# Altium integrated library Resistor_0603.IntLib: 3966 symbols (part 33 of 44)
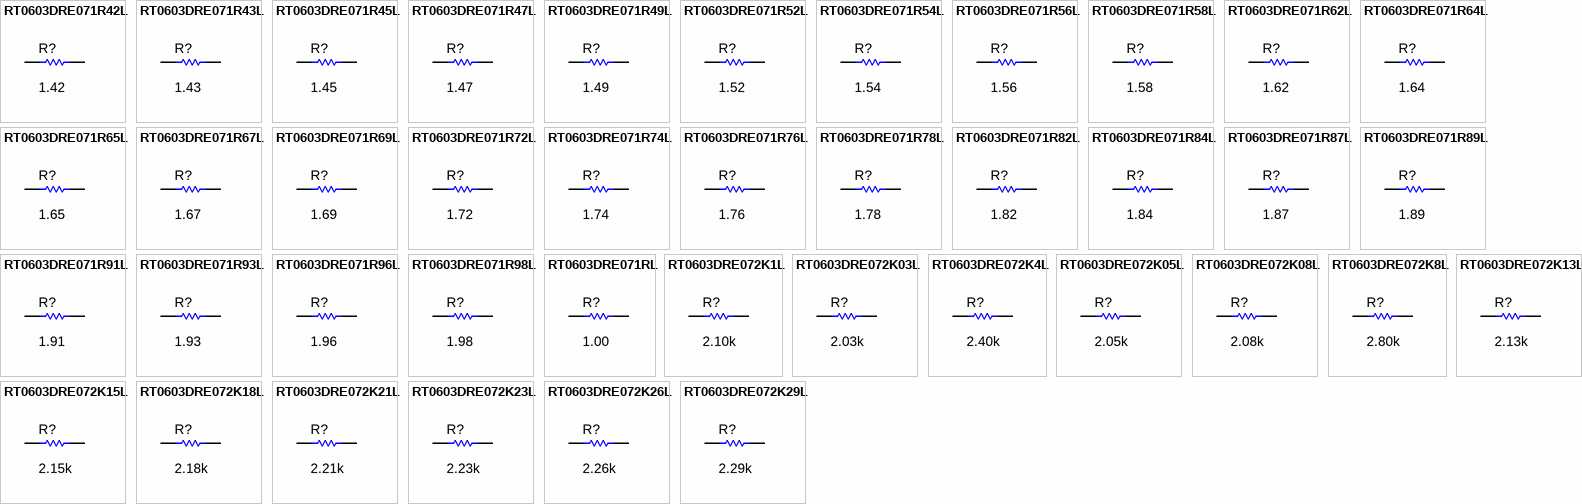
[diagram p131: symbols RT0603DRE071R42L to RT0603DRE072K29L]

## RT0603DRE071R49L
designator R?  ValueDisplayed: 1.49  (hidden comment: RT0603DRE071R49L)
RES, 1.49, 0.5%, 0.1 W, 0603; Manufacturer: Yageo America; CompType: Resistor; Value: 1.49; Value_Code: 1R49; Tolerance_%: 0.5; Power_W: 0.1; Value2: 0.1W; VDC_V: 75; TempCo: 50 ppm/C; SizeArea_mm2: 1.28; SizeX_mm: 1.6; SizeY_mm: 0.8; SizeZ_mm: 1; EIA_Code: E192; U/M: EA; AEC Category: Q200
signal-integrity model Resistor
simulation model Resistor
footprint 0603
footprint 0603M
footprint 0603L
footprint 0603_HV
footprint 0603S
pins: 1, 2

## RT0603DRE071R52L
designator R?  ValueDisplayed: 1.52  (hidden comment: RT0603DRE071R52L)
RES, 1.52, 0.5%, 0.1 W, 0603; Manufacturer: Yageo America; CompType: Resistor; Value: 1.52; Value_Code: 1R52; Tolerance_%: 0.5; Power_W: 0.1; Value2: 0.1W; VDC_V: 75; TempCo: 50 ppm/C; SizeArea_mm2: 1.28; SizeX_mm: 1.6; SizeY_mm: 0.8; SizeZ_mm: 1; EIA_Code: E192; U/M: EA; AEC Category: Q200
signal-integrity model Resistor
simulation model Resistor
footprint 0603
footprint 0603M
footprint 0603L
footprint 0603_HV
footprint 0603S
pins: 1, 2

## RT0603DRE071R54L
designator R?  ValueDisplayed: 1.54  (hidden comment: RT0603DRE071R54L)
RES, 1.54, 0.5%, 0.1 W, 0603; Manufacturer: Yageo America; CompType: Resistor; Value: 1.54; Value_Code: 1R54; Tolerance_%: 0.5; Power_W: 0.1; Value2: 0.1W; VDC_V: 75; TempCo: 50 ppm/C; SizeArea_mm2: 1.28; SizeX_mm: 1.6; SizeY_mm: 0.8; SizeZ_mm: 1; EIA_Code: E192; U/M: EA; AEC Category: Q200
signal-integrity model Resistor
simulation model Resistor
footprint 0603
footprint 0603M
footprint 0603L
footprint 0603_HV
footprint 0603S
pins: 1, 2

## RT0603DRE071R56L
designator R?  ValueDisplayed: 1.56  (hidden comment: RT0603DRE071R56L)
RES, 1.56, 0.5%, 0.1 W, 0603; Manufacturer: Yageo America; CompType: Resistor; Value: 1.56; Value_Code: 1R56; Tolerance_%: 0.5; Power_W: 0.1; Value2: 0.1W; VDC_V: 75; TempCo: 50 ppm/C; SizeArea_mm2: 1.28; SizeX_mm: 1.6; SizeY_mm: 0.8; SizeZ_mm: 1; EIA_Code: E192; U/M: EA; AEC Category: Q200
signal-integrity model Resistor
simulation model Resistor
footprint 0603
footprint 0603M
footprint 0603L
footprint 0603_HV
footprint 0603S
pins: 1, 2

## RT0603DRE071R58L
designator R?  ValueDisplayed: 1.58  (hidden comment: RT0603DRE071R58L)
RES, 1.58, 0.5%, 0.1 W, 0603; Manufacturer: Yageo America; CompType: Resistor; Value: 1.58; Value_Code: 1R58; Tolerance_%: 0.5; Power_W: 0.1; Value2: 0.1W; VDC_V: 75; TempCo: 50 ppm/C; SizeArea_mm2: 1.28; SizeX_mm: 1.6; SizeY_mm: 0.8; SizeZ_mm: 1; EIA_Code: E192; U/M: EA; AEC Category: Q200
signal-integrity model Resistor
simulation model Resistor
footprint 0603
footprint 0603M
footprint 0603L
footprint 0603_HV
footprint 0603S
pins: 1, 2

## RT0603DRE071R62L
designator R?  ValueDisplayed: 1.62  (hidden comment: RT0603DRE071R62L)
RES, 1.62, 0.5%, 0.1 W, 0603; Manufacturer: Yageo America; CompType: Resistor; Value: 1.62; Value_Code: 1R62; Tolerance_%: 0.5; Power_W: 0.1; Value2: 0.1W; VDC_V: 75; TempCo: 50 ppm/C; SizeArea_mm2: 1.28; SizeX_mm: 1.6; SizeY_mm: 0.8; SizeZ_mm: 1; EIA_Code: E192; U/M: EA; AEC Category: Q200
signal-integrity model Resistor
simulation model Resistor
footprint 0603
footprint 0603M
footprint 0603L
footprint 0603_HV
footprint 0603S
pins: 1, 2

## RT0603DRE071R64L
designator R?  ValueDisplayed: 1.64  (hidden comment: RT0603DRE071R64L)
RES, 1.64, 0.5%, 0.1 W, 0603; Manufacturer: Yageo America; CompType: Resistor; Value: 1.64; Value_Code: 1R64; Tolerance_%: 0.5; Power_W: 0.1; Value2: 0.1W; VDC_V: 75; TempCo: 50 ppm/C; SizeArea_mm2: 1.28; SizeX_mm: 1.6; SizeY_mm: 0.8; SizeZ_mm: 1; EIA_Code: E192; U/M: EA; AEC Category: Q200
signal-integrity model Resistor
simulation model Resistor
footprint 0603
footprint 0603M
footprint 0603L
footprint 0603_HV
footprint 0603S
pins: 1, 2

## RT0603DRE071R65L
designator R?  ValueDisplayed: 1.65  (hidden comment: RT0603DRE071R65L)
RES, 1.65, 0.5%, 0.1 W, 0603; Manufacturer: Yageo America; CompType: Resistor; Value: 1.65; Value_Code: 1R65; Tolerance_%: 0.5; Power_W: 0.1; Value2: 0.1W; VDC_V: 75; TempCo: 50 ppm/C; SizeArea_mm2: 1.28; SizeX_mm: 1.6; SizeY_mm: 0.8; SizeZ_mm: 1; EIA_Code: E192; U/M: EA; AEC Category: Q200
signal-integrity model Resistor
simulation model Resistor
footprint 0603
footprint 0603M
footprint 0603L
footprint 0603_HV
footprint 0603S
pins: 1, 2

## RT0603DRE071R67L
designator R?  ValueDisplayed: 1.67  (hidden comment: RT0603DRE071R67L)
RES, 1.67, 0.5%, 0.1 W, 0603; Manufacturer: Yageo America; CompType: Resistor; Value: 1.67; Value_Code: 1R67; Tolerance_%: 0.5; Power_W: 0.1; Value2: 0.1W; VDC_V: 75; TempCo: 50 ppm/C; SizeArea_mm2: 1.28; SizeX_mm: 1.6; SizeY_mm: 0.8; SizeZ_mm: 1; EIA_Code: E192; U/M: EA; AEC Category: Q200
signal-integrity model Resistor
simulation model Resistor
footprint 0603
footprint 0603M
footprint 0603L
footprint 0603_HV
footprint 0603S
pins: 1, 2

## RT0603DRE071R69L
designator R?  ValueDisplayed: 1.69  (hidden comment: RT0603DRE071R69L)
RES, 1.69, 0.5%, 0.1 W, 0603; Manufacturer: Yageo America; CompType: Resistor; Value: 1.69; Value_Code: 1R69; Tolerance_%: 0.5; Power_W: 0.1; Value2: 0.1W; VDC_V: 75; TempCo: 50 ppm/C; SizeArea_mm2: 1.28; SizeX_mm: 1.6; SizeY_mm: 0.8; SizeZ_mm: 1; EIA_Code: E192; U/M: EA; AEC Category: Q200
signal-integrity model Resistor
simulation model Resistor
footprint 0603
footprint 0603M
footprint 0603L
footprint 0603_HV
footprint 0603S
pins: 1, 2

## RT0603DRE071R72L
designator R?  ValueDisplayed: 1.72  (hidden comment: RT0603DRE071R72L)
RES, 1.72, 0.5%, 0.1 W, 0603; Manufacturer: Yageo America; CompType: Resistor; Value: 1.72; Value_Code: 1R72; Tolerance_%: 0.5; Power_W: 0.1; Value2: 0.1W; VDC_V: 75; TempCo: 50 ppm/C; SizeArea_mm2: 1.28; SizeX_mm: 1.6; SizeY_mm: 0.8; SizeZ_mm: 1; EIA_Code: E192; U/M: EA; AEC Category: Q200
signal-integrity model Resistor
simulation model Resistor
footprint 0603
footprint 0603M
footprint 0603L
footprint 0603_HV
footprint 0603S
pins: 1, 2

## RT0603DRE071R74L
designator R?  ValueDisplayed: 1.74  (hidden comment: RT0603DRE071R74L)
RES, 1.74, 0.5%, 0.1 W, 0603; Manufacturer: Yageo America; CompType: Resistor; Value: 1.74; Value_Code: 1R74; Tolerance_%: 0.5; Power_W: 0.1; Value2: 0.1W; VDC_V: 75; TempCo: 50 ppm/C; SizeArea_mm2: 1.28; SizeX_mm: 1.6; SizeY_mm: 0.8; SizeZ_mm: 1; EIA_Code: E192; U/M: EA; AEC Category: Q200
signal-integrity model Resistor
simulation model Resistor
footprint 0603
footprint 0603M
footprint 0603L
footprint 0603_HV
footprint 0603S
pins: 1, 2

## RT0603DRE071R76L
designator R?  ValueDisplayed: 1.76  (hidden comment: RT0603DRE071R76L)
RES, 1.76, 0.5%, 0.1 W, 0603; Manufacturer: Yageo America; CompType: Resistor; Value: 1.76; Value_Code: 1R76; Tolerance_%: 0.5; Power_W: 0.1; Value2: 0.1W; VDC_V: 75; TempCo: 50 ppm/C; SizeArea_mm2: 1.28; SizeX_mm: 1.6; SizeY_mm: 0.8; SizeZ_mm: 1; EIA_Code: E192; U/M: EA; AEC Category: Q200
signal-integrity model Resistor
simulation model Resistor
footprint 0603
footprint 0603M
footprint 0603L
footprint 0603_HV
footprint 0603S
pins: 1, 2

## RT0603DRE071R78L
designator R?  ValueDisplayed: 1.78  (hidden comment: RT0603DRE071R78L)
RES, 1.78, 0.5%, 0.1 W, 0603; Manufacturer: Yageo America; CompType: Resistor; Value: 1.78; Value_Code: 1R78; Tolerance_%: 0.5; Power_W: 0.1; Value2: 0.1W; VDC_V: 75; TempCo: 50 ppm/C; SizeArea_mm2: 1.28; SizeX_mm: 1.6; SizeY_mm: 0.8; SizeZ_mm: 1; EIA_Code: E192; U/M: EA; AEC Category: Q200
signal-integrity model Resistor
simulation model Resistor
footprint 0603
footprint 0603M
footprint 0603L
footprint 0603_HV
footprint 0603S
pins: 1, 2

## RT0603DRE071R82L
designator R?  ValueDisplayed: 1.82  (hidden comment: RT0603DRE071R82L)
RES, 1.82, 0.5%, 0.1 W, 0603; Manufacturer: Yageo America; CompType: Resistor; Value: 1.82; Value_Code: 1R82; Tolerance_%: 0.5; Power_W: 0.1; Value2: 0.1W; VDC_V: 75; TempCo: 50 ppm/C; SizeArea_mm2: 1.28; SizeX_mm: 1.6; SizeY_mm: 0.8; SizeZ_mm: 1; EIA_Code: E192; U/M: EA; AEC Category: Q200
signal-integrity model Resistor
simulation model Resistor
footprint 0603
footprint 0603M
footprint 0603L
footprint 0603_HV
footprint 0603S
pins: 1, 2

## RT0603DRE071R84L
designator R?  ValueDisplayed: 1.84  (hidden comment: RT0603DRE071R84L)
RES, 1.84, 0.5%, 0.1 W, 0603; Manufacturer: Yageo America; CompType: Resistor; Value: 1.84; Value_Code: 1R84; Tolerance_%: 0.5; Power_W: 0.1; Value2: 0.1W; VDC_V: 75; TempCo: 50 ppm/C; SizeArea_mm2: 1.28; SizeX_mm: 1.6; SizeY_mm: 0.8; SizeZ_mm: 1; EIA_Code: E192; U/M: EA; AEC Category: Q200
signal-integrity model Resistor
simulation model Resistor
footprint 0603
footprint 0603M
footprint 0603L
footprint 0603_HV
footprint 0603S
pins: 1, 2

## RT0603DRE071R87L
designator R?  ValueDisplayed: 1.87  (hidden comment: RT0603DRE071R87L)
RES, 1.87, 0.5%, 0.1 W, 0603; Manufacturer: Yageo America; CompType: Resistor; Value: 1.87; Value_Code: 1R87; Tolerance_%: 0.5; Power_W: 0.1; Value2: 0.1W; VDC_V: 75; TempCo: 50 ppm/C; SizeArea_mm2: 1.28; SizeX_mm: 1.6; SizeY_mm: 0.8; SizeZ_mm: 1; EIA_Code: E192; U/M: EA; AEC Category: Q200
signal-integrity model Resistor
simulation model Resistor
footprint 0603
footprint 0603M
footprint 0603L
footprint 0603_HV
footprint 0603S
pins: 1, 2

## RT0603DRE071R89L
designator R?  ValueDisplayed: 1.89  (hidden comment: RT0603DRE071R89L)
RES, 1.89, 0.5%, 0.1 W, 0603; Manufacturer: Yageo America; CompType: Resistor; Value: 1.89; Value_Code: 1R89; Tolerance_%: 0.5; Power_W: 0.1; Value2: 0.1W; VDC_V: 75; TempCo: 50 ppm/C; SizeArea_mm2: 1.28; SizeX_mm: 1.6; SizeY_mm: 0.8; SizeZ_mm: 1; EIA_Code: E192; U/M: EA; AEC Category: Q200
signal-integrity model Resistor
simulation model Resistor
footprint 0603
footprint 0603M
footprint 0603L
footprint 0603_HV
footprint 0603S
pins: 1, 2

## RT0603DRE071R91L
designator R?  ValueDisplayed: 1.91  (hidden comment: RT0603DRE071R91L)
RES, 1.91, 0.5%, 0.1 W, 0603; Manufacturer: Yageo America; CompType: Resistor; Value: 1.91; Value_Code: 1R91; Tolerance_%: 0.5; Power_W: 0.1; Value2: 0.1W; VDC_V: 75; TempCo: 50 ppm/C; SizeArea_mm2: 1.28; SizeX_mm: 1.6; SizeY_mm: 0.8; SizeZ_mm: 1; EIA_Code: E192; U/M: EA; AEC Category: Q200
signal-integrity model Resistor
simulation model Resistor
footprint 0603
footprint 0603M
footprint 0603L
footprint 0603_HV
footprint 0603S
pins: 1, 2

## RT0603DRE071R93L
designator R?  ValueDisplayed: 1.93  (hidden comment: RT0603DRE071R93L)
RES, 1.93, 0.5%, 0.1 W, 0603; Manufacturer: Yageo America; CompType: Resistor; Value: 1.93; Value_Code: 1R93; Tolerance_%: 0.5; Power_W: 0.1; Value2: 0.1W; VDC_V: 75; TempCo: 50 ppm/C; SizeArea_mm2: 1.28; SizeX_mm: 1.6; SizeY_mm: 0.8; SizeZ_mm: 1; EIA_Code: E192; U/M: EA; AEC Category: Q200
signal-integrity model Resistor
simulation model Resistor
footprint 0603
footprint 0603M
footprint 0603L
footprint 0603_HV
footprint 0603S
pins: 1, 2

## RT0603DRE071R96L
designator R?  ValueDisplayed: 1.96  (hidden comment: RT0603DRE071R96L)
RES, 1.96, 0.5%, 0.1 W, 0603; Manufacturer: Yageo America; CompType: Resistor; Value: 1.96; Value_Code: 1R96; Tolerance_%: 0.5; Power_W: 0.1; Value2: 0.1W; VDC_V: 75; TempCo: 50 ppm/C; SizeArea_mm2: 1.28; SizeX_mm: 1.6; SizeY_mm: 0.8; SizeZ_mm: 1; EIA_Code: E192; U/M: EA; AEC Category: Q200
signal-integrity model Resistor
simulation model Resistor
footprint 0603
footprint 0603M
footprint 0603L
footprint 0603_HV
footprint 0603S
pins: 1, 2

## RT0603DRE071R98L
designator R?  ValueDisplayed: 1.98  (hidden comment: RT0603DRE071R98L)
RES, 1.98, 0.5%, 0.1 W, 0603; Manufacturer: Yageo America; CompType: Resistor; Value: 1.98; Value_Code: 1R98; Tolerance_%: 0.5; Power_W: 0.1; Value2: 0.1W; VDC_V: 75; TempCo: 50 ppm/C; SizeArea_mm2: 1.28; SizeX_mm: 1.6; SizeY_mm: 0.8; SizeZ_mm: 1; EIA_Code: E192; U/M: EA; AEC Category: Q200
signal-integrity model Resistor
simulation model Resistor
footprint 0603
footprint 0603M
footprint 0603L
footprint 0603_HV
footprint 0603S
pins: 1, 2

## RT0603DRE071RL
designator R?  ValueDisplayed: 1.00  (hidden comment: RT0603DRE071RL)
RES, 1.00, 0.5%, 0.1 W, 0603; Manufacturer: Yageo America; CompType: Resistor; Value: 1.00; Res_ohm: 1; Value_Code: 1R00; Tolerance_%: 0.5; Power_W: 0.1; Value2: 0.1W; VDC_V: 75; TempCo: 50 ppm/C; SizeArea_mm2: 1.28; SizeX_mm: 1.6; SizeY_mm: 0.8; EIA_Code: E192; U/M: EA; AEC Category: Q200; Green_Lifecycle: Active; Green_REACh: Passed
signal-integrity model Resistor
simulation model Resistor
footprint 0603
footprint 0603M
footprint 0603L
footprint 0603_HV
footprint 0603S
pins: 1, 2

## RT0603DRE072K1L
designator R?  ValueDisplayed: 2.10k  (hidden comment: RT0603DRE072K1L)
RES, 2.10 k, 0.5%, 0.1 W, 0603; Manufacturer: Yageo America; CompType: Resistor; Value: 2.10k; Res_ohm: 2100; Value_Code: 2k10; Tolerance_%: 0.5; Power_W: 0.1; Value2: 0.1W; VDC_V: 75; TempCo: 50 ppm/C; SizeArea_mm2: 1.28; SizeX_mm: 1.6; SizeY_mm: 0.8; SizeZ_mm: 1; EIA_Code: E192; U/M: EA; AEC Category: Q200
signal-integrity model Resistor
simulation model Resistor
footprint 0603
footprint 0603M
footprint 0603L
footprint 0603_HV
footprint 0603S
pins: 1, 2

## RT0603DRE072K03L
designator R?  ValueDisplayed: 2.03k  (hidden comment: RT0603DRE072K03L)
RES, 2.03 k, 0.5%, 0.1 W, 0603; Manufacturer: Yageo America; CompType: Resistor; Value: 2.03k; Res_ohm: 2030; Value_Code: 2k03; Tolerance_%: 0.5; Power_W: 0.1; Value2: 0.1W; VDC_V: 75; TempCo: 50 ppm/C; SizeArea_mm2: 1.28; SizeX_mm: 1.6; SizeY_mm: 0.8; SizeZ_mm: 1; EIA_Code: E192; U/M: EA; AEC Category: Q200
signal-integrity model Resistor
simulation model Resistor
footprint 0603
footprint 0603M
footprint 0603L
footprint 0603_HV
footprint 0603S
pins: 1, 2

## RT0603DRE072K4L
designator R?  ValueDisplayed: 2.40k  (hidden comment: RT0603DRE072K4L)
RES, 2.40 k, 0.5%, 0.1 W, 0603; Manufacturer: Yageo America; CompType: Resistor; Value: 2.40k; Res_ohm: 2400; Value_Code: 2k40; Tolerance_%: 0.5; Power_W: 0.1; Value2: 0.1W; VDC_V: 75; TempCo: 50 ppm/C; SizeArea_mm2: 1.28; SizeX_mm: 1.6; SizeY_mm: 0.8; SizeZ_mm: 1; EIA_Code: E192; U/M: EA; AEC Category: Q200
signal-integrity model Resistor
simulation model Resistor
footprint 0603
footprint 0603M
footprint 0603L
footprint 0603_HV
footprint 0603S
pins: 1, 2

## RT0603DRE072K05L
designator R?  ValueDisplayed: 2.05k  (hidden comment: RT0603DRE072K05L)
RES, 2.05 k, 0.5%, 0.1 W, 0603; Manufacturer: Yageo America; CompType: Resistor; Value: 2.05k; Res_ohm: 2050; Value_Code: 2k05; Tolerance_%: 0.5; Power_W: 0.1; Value2: 0.1W; VDC_V: 75; TempCo: 50 ppm/C; SizeArea_mm2: 1.28; SizeX_mm: 1.6; SizeY_mm: 0.8; SizeZ_mm: 1; EIA_Code: E192; U/M: EA; AEC Category: Q200
signal-integrity model Resistor
simulation model Resistor
footprint 0603
footprint 0603M
footprint 0603L
footprint 0603_HV
footprint 0603S
pins: 1, 2

## RT0603DRE072K08L
designator R?  ValueDisplayed: 2.08k  (hidden comment: RT0603DRE072K08L)
RES, 2.08 k, 0.5%, 0.1 W, 0603; Manufacturer: Yageo America; CompType: Resistor; Value: 2.08k; Res_ohm: 2080; Value_Code: 2k08; Tolerance_%: 0.5; Power_W: 0.1; Value2: 0.1W; VDC_V: 75; TempCo: 50 ppm/C; SizeArea_mm2: 1.28; SizeX_mm: 1.6; SizeY_mm: 0.8; SizeZ_mm: 1; EIA_Code: E192; U/M: EA; AEC Category: Q200
signal-integrity model Resistor
simulation model Resistor
footprint 0603
footprint 0603M
footprint 0603L
footprint 0603_HV
footprint 0603S
pins: 1, 2

## RT0603DRE072K8L
designator R?  ValueDisplayed: 2.80k  (hidden comment: RT0603DRE072K8L)
RES, 2.80 k, 0.5%, 0.1 W, 0603; Manufacturer: Yageo America; CompType: Resistor; Value: 2.80k; Res_ohm: 2800; Value_Code: 2k80; Tolerance_%: 0.5; Power_W: 0.1; Value2: 0.1W; VDC_V: 75; TempCo: 50 ppm/C; SizeArea_mm2: 1.28; SizeX_mm: 1.6; SizeY_mm: 0.8; SizeZ_mm: 1; EIA_Code: E192; U/M: EA; AEC Category: Q200
signal-integrity model Resistor
simulation model Resistor
footprint 0603
footprint 0603M
footprint 0603L
footprint 0603_HV
footprint 0603S
pins: 1, 2

## RT0603DRE072K13L
designator R?  ValueDisplayed: 2.13k  (hidden comment: RT0603DRE072K13L)
RES, 2.13 k, 0.5%, 0.1 W, 0603; Manufacturer: Yageo America; CompType: Resistor; Value: 2.13k; Res_ohm: 2130; Value_Code: 2k13; Tolerance_%: 0.5; Power_W: 0.1; Value2: 0.1W; VDC_V: 75; TempCo: 50 ppm/C; SizeArea_mm2: 1.28; SizeX_mm: 1.6; SizeY_mm: 0.8; SizeZ_mm: 1; EIA_Code: E192; U/M: EA; AEC Category: Q200
signal-integrity model Resistor
simulation model Resistor
footprint 0603
footprint 0603M
footprint 0603L
footprint 0603_HV
footprint 0603S
pins: 1, 2

## RT0603DRE072K15L
designator R?  ValueDisplayed: 2.15k  (hidden comment: RT0603DRE072K15L)
RES, 2.15 k, 0.5%, 0.1 W, 0603; Manufacturer: Yageo America; CompType: Resistor; Value: 2.15k; Res_ohm: 2150; Value_Code: 2k15; Tolerance_%: 0.5; Power_W: 0.1; Value2: 0.1W; VDC_V: 75; TempCo: 50 ppm/C; SizeArea_mm2: 1.28; SizeX_mm: 1.6; SizeY_mm: 0.8; SizeZ_mm: 1; EIA_Code: E192; U/M: EA; AEC Category: Q200
signal-integrity model Resistor
simulation model Resistor
footprint 0603
footprint 0603M
footprint 0603L
footprint 0603_HV
footprint 0603S
pins: 1, 2

## RT0603DRE072K18L
designator R?  ValueDisplayed: 2.18k  (hidden comment: RT0603DRE072K18L)
RES, 2.18 k, 0.5%, 0.1 W, 0603; Manufacturer: Yageo America; CompType: Resistor; Value: 2.18k; Res_ohm: 2180; Value_Code: 2k18; Tolerance_%: 0.5; Power_W: 0.1; Value2: 0.1W; VDC_V: 75; TempCo: 50 ppm/C; SizeArea_mm2: 1.28; SizeX_mm: 1.6; SizeY_mm: 0.8; SizeZ_mm: 1; EIA_Code: E192; U/M: EA; AEC Category: Q200
signal-integrity model Resistor
simulation model Resistor
footprint 0603
footprint 0603M
footprint 0603L
footprint 0603_HV
footprint 0603S
pins: 1, 2

## RT0603DRE072K21L
designator R?  ValueDisplayed: 2.21k  (hidden comment: RT0603DRE072K21L)
RES, 2.21 k, 0.5%, 0.1 W, 0603; Manufacturer: Yageo America; CompType: Resistor; Value: 2.21k; Res_ohm: 2210; Value_Code: 2k21; Tolerance_%: 0.5; Power_W: 0.1; Value2: 0.1W; VDC_V: 75; TempCo: 50 ppm/C; SizeArea_mm2: 1.28; SizeX_mm: 1.6; SizeY_mm: 0.8; SizeZ_mm: 1; EIA_Code: E192; U/M: EA; AEC Category: Q200
signal-integrity model Resistor
simulation model Resistor
footprint 0603
footprint 0603M
footprint 0603L
footprint 0603_HV
footprint 0603S
pins: 1, 2

## RT0603DRE072K23L
designator R?  ValueDisplayed: 2.23k  (hidden comment: RT0603DRE072K23L)
RES, 2.23 k, 0.5%, 0.1 W, 0603; Manufacturer: Yageo America; CompType: Resistor; Value: 2.23k; Res_ohm: 2230; Value_Code: 2k23; Tolerance_%: 0.5; Power_W: 0.1; Value2: 0.1W; VDC_V: 75; TempCo: 50 ppm/C; SizeArea_mm2: 1.28; SizeX_mm: 1.6; SizeY_mm: 0.8; SizeZ_mm: 1; EIA_Code: E192; U/M: EA; AEC Category: Q200
signal-integrity model Resistor
simulation model Resistor
footprint 0603
footprint 0603M
footprint 0603L
footprint 0603_HV
footprint 0603S
pins: 1, 2

## RT0603DRE072K26L
designator R?  ValueDisplayed: 2.26k  (hidden comment: RT0603DRE072K26L)
RES, 2.26 k, 0.5%, 0.1 W, 0603; Manufacturer: Yageo America; CompType: Resistor; Value: 2.26k; Res_ohm: 2260; Value_Code: 2k26; Tolerance_%: 0.5; Power_W: 0.1; Value2: 0.1W; VDC_V: 75; TempCo: 50 ppm/C; SizeArea_mm2: 1.28; SizeX_mm: 1.6; SizeY_mm: 0.8; SizeZ_mm: 1; EIA_Code: E192; U/M: EA; AEC Category: Q200
signal-integrity model Resistor
simulation model Resistor
footprint 0603
footprint 0603M
footprint 0603L
footprint 0603_HV
footprint 0603S
pins: 1, 2

## RT0603DRE072K29L
designator R?  ValueDisplayed: 2.29k  (hidden comment: RT0603DRE072K29L)
RES, 2.29 k, 0.5%, 0.1 W, 0603; Manufacturer: Yageo America; CompType: Resistor; Value: 2.29k; Res_ohm: 2290; Value_Code: 2k29; Tolerance_%: 0.5; Power_W: 0.1; Value2: 0.1W; VDC_V: 75; TempCo: 50 ppm/C; SizeArea_mm2: 1.28; SizeX_mm: 1.6; SizeY_mm: 0.8; SizeZ_mm: 1; EIA_Code: E192; U/M: EA; AEC Category: Q200
signal-integrity model Resistor
simulation model Resistor
footprint 0603
footprint 0603M
footprint 0603L
footprint 0603_HV
footprint 0603S
pins: 1, 2

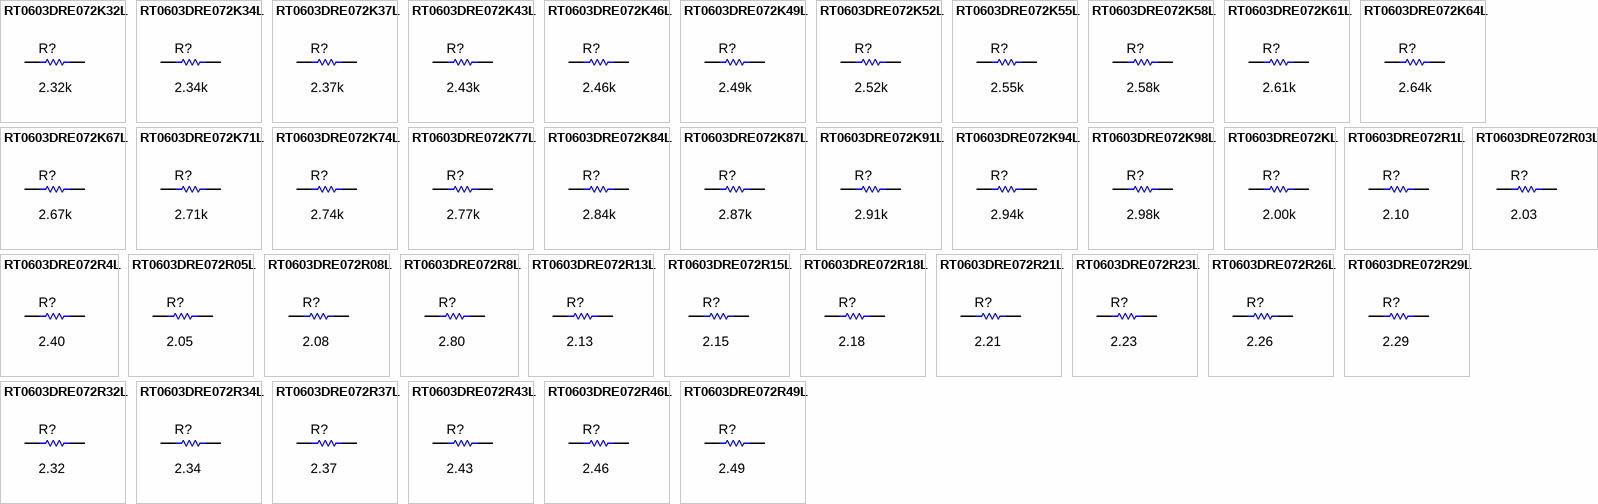
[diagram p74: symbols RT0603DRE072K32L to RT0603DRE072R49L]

## RT0603DRE072K32L
designator R?  ValueDisplayed: 2.32k  (hidden comment: RT0603DRE072K32L)
RES, 2.32 k, 0.5%, 0.1 W, 0603; Manufacturer: Yageo America; CompType: Resistor; Value: 2.32k; Res_ohm: 2320; Value_Code: 2k32; Tolerance_%: 0.5; Power_W: 0.1; Value2: 0.1W; VDC_V: 75; TempCo: 50 ppm/C; SizeArea_mm2: 1.28; SizeX_mm: 1.6; SizeY_mm: 0.8; SizeZ_mm: 1; EIA_Code: E192; U/M: EA; AEC Category: Q200
signal-integrity model Resistor
simulation model Resistor
footprint 0603
footprint 0603M
footprint 0603L
footprint 0603_HV
footprint 0603S
pins: 1, 2

## RT0603DRE072K34L
designator R?  ValueDisplayed: 2.34k  (hidden comment: RT0603DRE072K34L)
RES, 2.34 k, 0.5%, 0.1 W, 0603; Manufacturer: Yageo America; CompType: Resistor; Value: 2.34k; Res_ohm: 2340; Value_Code: 2k34; Tolerance_%: 0.5; Power_W: 0.1; Value2: 0.1W; VDC_V: 75; TempCo: 50 ppm/C; SizeArea_mm2: 1.28; SizeX_mm: 1.6; SizeY_mm: 0.8; SizeZ_mm: 1; EIA_Code: E192; U/M: EA; AEC Category: Q200
signal-integrity model Resistor
simulation model Resistor
footprint 0603
footprint 0603M
footprint 0603L
footprint 0603_HV
footprint 0603S
pins: 1, 2

## RT0603DRE072K37L
designator R?  ValueDisplayed: 2.37k  (hidden comment: RT0603DRE072K37L)
RES, 2.37 k, 0.5%, 0.1 W, 0603; Manufacturer: Yageo America; CompType: Resistor; Value: 2.37k; Res_ohm: 2370; Value_Code: 2k37; Tolerance_%: 0.5; Power_W: 0.1; Value2: 0.1W; VDC_V: 75; TempCo: 50 ppm/C; SizeArea_mm2: 1.28; SizeX_mm: 1.6; SizeY_mm: 0.8; SizeZ_mm: 1; EIA_Code: E192; U/M: EA; AEC Category: Q200
signal-integrity model Resistor
simulation model Resistor
footprint 0603
footprint 0603M
footprint 0603L
footprint 0603_HV
footprint 0603S
pins: 1, 2

## RT0603DRE072K43L
designator R?  ValueDisplayed: 2.43k  (hidden comment: RT0603DRE072K43L)
RES, 2.43 k, 0.5%, 0.1 W, 0603; Manufacturer: Yageo America; CompType: Resistor; Value: 2.43k; Res_ohm: 2430; Value_Code: 2k43; Tolerance_%: 0.5; Power_W: 0.1; Value2: 0.1W; VDC_V: 75; TempCo: 50 ppm/C; SizeArea_mm2: 1.28; SizeX_mm: 1.6; SizeY_mm: 0.8; SizeZ_mm: 1; EIA_Code: E192; U/M: EA; AEC Category: Q200
signal-integrity model Resistor
simulation model Resistor
footprint 0603
footprint 0603M
footprint 0603L
footprint 0603_HV
footprint 0603S
pins: 1, 2

## RT0603DRE072K46L
designator R?  ValueDisplayed: 2.46k  (hidden comment: RT0603DRE072K46L)
RES, 2.46 k, 0.5%, 0.1 W, 0603; Manufacturer: Yageo America; CompType: Resistor; Value: 2.46k; Res_ohm: 2460; Value_Code: 2k46; Tolerance_%: 0.5; Power_W: 0.1; Value2: 0.1W; VDC_V: 75; TempCo: 50 ppm/C; SizeArea_mm2: 1.28; SizeX_mm: 1.6; SizeY_mm: 0.8; SizeZ_mm: 1; EIA_Code: E192; U/M: EA; AEC Category: Q200
signal-integrity model Resistor
simulation model Resistor
footprint 0603
footprint 0603M
footprint 0603L
footprint 0603_HV
footprint 0603S
pins: 1, 2

## RT0603DRE072K49L
designator R?  ValueDisplayed: 2.49k  (hidden comment: RT0603DRE072K49L)
RES, 2.49 k, 0.5%, 0.1 W, 0603; Manufacturer: Yageo America; CompType: Resistor; Value: 2.49k; Res_ohm: 2490; Value_Code: 2k49; Tolerance_%: 0.5; Power_W: 0.1; Value2: 0.1W; VDC_V: 75; TempCo: 50 ppm/C; SizeArea_mm2: 1.28; SizeX_mm: 1.6; SizeY_mm: 0.8; SizeZ_mm: 1; EIA_Code: E192; U/M: EA; AEC Category: Q200
signal-integrity model Resistor
simulation model Resistor
footprint 0603
footprint 0603M
footprint 0603L
footprint 0603_HV
footprint 0603S
pins: 1, 2

## RT0603DRE072K52L
designator R?  ValueDisplayed: 2.52k  (hidden comment: RT0603DRE072K52L)
RES, 2.52 k, 0.5%, 0.1 W, 0603; Manufacturer: Yageo America; CompType: Resistor; Value: 2.52k; Res_ohm: 2520; Value_Code: 2k52; Tolerance_%: 0.5; Power_W: 0.1; Value2: 0.1W; VDC_V: 75; TempCo: 50 ppm/C; SizeArea_mm2: 1.28; SizeX_mm: 1.6; SizeY_mm: 0.8; SizeZ_mm: 1; EIA_Code: E192; U/M: EA; AEC Category: Q200
signal-integrity model Resistor
simulation model Resistor
footprint 0603
footprint 0603M
footprint 0603L
footprint 0603_HV
footprint 0603S
pins: 1, 2

## RT0603DRE072K55L
designator R?  ValueDisplayed: 2.55k  (hidden comment: RT0603DRE072K55L)
RES, 2.55 k, 0.5%, 0.1 W, 0603; Manufacturer: Yageo America; CompType: Resistor; Value: 2.55k; Res_ohm: 2550; Value_Code: 2k55; Tolerance_%: 0.5; Power_W: 0.1; Value2: 0.1W; VDC_V: 75; TempCo: 50 ppm/C; SizeArea_mm2: 1.28; SizeX_mm: 1.6; SizeY_mm: 0.8; SizeZ_mm: 1; EIA_Code: E192; U/M: EA; AEC Category: Q200
signal-integrity model Resistor
simulation model Resistor
footprint 0603
footprint 0603M
footprint 0603L
footprint 0603_HV
footprint 0603S
pins: 1, 2

## RT0603DRE072K58L
designator R?  ValueDisplayed: 2.58k  (hidden comment: RT0603DRE072K58L)
RES, 2.58 k, 0.5%, 0.1 W, 0603; Manufacturer: Yageo America; CompType: Resistor; Value: 2.58k; Res_ohm: 2580; Value_Code: 2k58; Tolerance_%: 0.5; Power_W: 0.1; Value2: 0.1W; VDC_V: 75; TempCo: 50 ppm/C; SizeArea_mm2: 1.28; SizeX_mm: 1.6; SizeY_mm: 0.8; SizeZ_mm: 1; EIA_Code: E192; U/M: EA; AEC Category: Q200
signal-integrity model Resistor
simulation model Resistor
footprint 0603
footprint 0603M
footprint 0603L
footprint 0603_HV
footprint 0603S
pins: 1, 2

## RT0603DRE072K61L
designator R?  ValueDisplayed: 2.61k  (hidden comment: RT0603DRE072K61L)
RES, 2.61 k, 0.5%, 0.1 W, 0603; Manufacturer: Yageo America; CompType: Resistor; Value: 2.61k; Res_ohm: 2610; Value_Code: 2k61; Tolerance_%: 0.5; Power_W: 0.1; Value2: 0.1W; VDC_V: 75; TempCo: 50 ppm/C; SizeArea_mm2: 1.28; SizeX_mm: 1.6; SizeY_mm: 0.8; SizeZ_mm: 1; EIA_Code: E192; U/M: EA; AEC Category: Q200
signal-integrity model Resistor
simulation model Resistor
footprint 0603
footprint 0603M
footprint 0603L
footprint 0603_HV
footprint 0603S
pins: 1, 2

## RT0603DRE072K64L
designator R?  ValueDisplayed: 2.64k  (hidden comment: RT0603DRE072K64L)
RES, 2.64 k, 0.5%, 0.1 W, 0603; Manufacturer: Yageo America; CompType: Resistor; Value: 2.64k; Res_ohm: 2640; Value_Code: 2k64; Tolerance_%: 0.5; Power_W: 0.1; Value2: 0.1W; VDC_V: 75; TempCo: 50 ppm/C; SizeArea_mm2: 1.28; SizeX_mm: 1.6; SizeY_mm: 0.8; SizeZ_mm: 1; EIA_Code: E192; U/M: EA; AEC Category: Q200
signal-integrity model Resistor
simulation model Resistor
footprint 0603
footprint 0603M
footprint 0603L
footprint 0603_HV
footprint 0603S
pins: 1, 2

## RT0603DRE072K67L
designator R?  ValueDisplayed: 2.67k  (hidden comment: RT0603DRE072K67L)
RES, 2.67 k, 0.5%, 0.1 W, 0603; Manufacturer: Yageo America; CompType: Resistor; Value: 2.67k; Res_ohm: 2670; Value_Code: 2k67; Tolerance_%: 0.5; Power_W: 0.1; Value2: 0.1W; VDC_V: 75; TempCo: 50 ppm/C; SizeArea_mm2: 1.28; SizeX_mm: 1.6; SizeY_mm: 0.8; SizeZ_mm: 1; EIA_Code: E192; U/M: EA; AEC Category: Q200
signal-integrity model Resistor
simulation model Resistor
footprint 0603
footprint 0603M
footprint 0603L
footprint 0603_HV
footprint 0603S
pins: 1, 2

## RT0603DRE072K71L
designator R?  ValueDisplayed: 2.71k  (hidden comment: RT0603DRE072K71L)
RES, 2.71 k, 0.5%, 0.1 W, 0603; Manufacturer: Yageo America; CompType: Resistor; Value: 2.71k; Res_ohm: 2710; Value_Code: 2k71; Tolerance_%: 0.5; Power_W: 0.1; Value2: 0.1W; VDC_V: 75; TempCo: 50 ppm/C; SizeArea_mm2: 1.28; SizeX_mm: 1.6; SizeY_mm: 0.8; SizeZ_mm: 1; EIA_Code: E192; U/M: EA; AEC Category: Q200
signal-integrity model Resistor
simulation model Resistor
footprint 0603
footprint 0603M
footprint 0603L
footprint 0603_HV
footprint 0603S
pins: 1, 2

## RT0603DRE072K74L
designator R?  ValueDisplayed: 2.74k  (hidden comment: RT0603DRE072K74L)
RES, 2.74 k, 0.5%, 0.1 W, 0603; Manufacturer: Yageo America; CompType: Resistor; Value: 2.74k; Res_ohm: 2740; Value_Code: 2k74; Tolerance_%: 0.5; Power_W: 0.1; Value2: 0.1W; VDC_V: 75; TempCo: 50 ppm/C; SizeArea_mm2: 1.28; SizeX_mm: 1.6; SizeY_mm: 0.8; SizeZ_mm: 1; EIA_Code: E192; U/M: EA; AEC Category: Q200
signal-integrity model Resistor
simulation model Resistor
footprint 0603
footprint 0603M
footprint 0603L
footprint 0603_HV
footprint 0603S
pins: 1, 2

## RT0603DRE072K77L
designator R?  ValueDisplayed: 2.77k  (hidden comment: RT0603DRE072K77L)
RES, 2.77 k, 0.5%, 0.1 W, 0603; Manufacturer: Yageo America; CompType: Resistor; Value: 2.77k; Res_ohm: 2770; Value_Code: 2k77; Tolerance_%: 0.5; Power_W: 0.1; Value2: 0.1W; VDC_V: 75; TempCo: 50 ppm/C; SizeArea_mm2: 1.28; SizeX_mm: 1.6; SizeY_mm: 0.8; SizeZ_mm: 1; EIA_Code: E192; U/M: EA; AEC Category: Q200
signal-integrity model Resistor
simulation model Resistor
footprint 0603
footprint 0603M
footprint 0603L
footprint 0603_HV
footprint 0603S
pins: 1, 2

## RT0603DRE072K84L
designator R?  ValueDisplayed: 2.84k  (hidden comment: RT0603DRE072K84L)
RES, 2.84 k, 0.5%, 0.1 W, 0603; Manufacturer: Yageo America; CompType: Resistor; Value: 2.84k; Res_ohm: 2840; Value_Code: 2k84; Tolerance_%: 0.5; Power_W: 0.1; Value2: 0.1W; VDC_V: 75; TempCo: 50 ppm/C; SizeArea_mm2: 1.28; SizeX_mm: 1.6; SizeY_mm: 0.8; SizeZ_mm: 1; EIA_Code: E192; U/M: EA; AEC Category: Q200
signal-integrity model Resistor
simulation model Resistor
footprint 0603
footprint 0603M
footprint 0603L
footprint 0603_HV
footprint 0603S
pins: 1, 2

## RT0603DRE072K87L
designator R?  ValueDisplayed: 2.87k  (hidden comment: RT0603DRE072K87L)
RES, 2.87 k, 0.5%, 0.1 W, 0603; Manufacturer: Yageo America; CompType: Resistor; Value: 2.87k; Res_ohm: 2870; Value_Code: 2k87; Tolerance_%: 0.5; Power_W: 0.1; Value2: 0.1W; VDC_V: 75; TempCo: 50 ppm/C; SizeArea_mm2: 1.28; SizeX_mm: 1.6; SizeY_mm: 0.8; SizeZ_mm: 1; EIA_Code: E192; U/M: EA; AEC Category: Q200
signal-integrity model Resistor
simulation model Resistor
footprint 0603
footprint 0603M
footprint 0603L
footprint 0603_HV
footprint 0603S
pins: 1, 2

## RT0603DRE072K91L
designator R?  ValueDisplayed: 2.91k  (hidden comment: RT0603DRE072K91L)
RES, 2.91 k, 0.5%, 0.1 W, 0603; Manufacturer: Yageo America; CompType: Resistor; Value: 2.91k; Res_ohm: 2910; Value_Code: 2k91; Tolerance_%: 0.5; Power_W: 0.1; Value2: 0.1W; VDC_V: 75; TempCo: 50 ppm/C; SizeArea_mm2: 1.28; SizeX_mm: 1.6; SizeY_mm: 0.8; SizeZ_mm: 1; EIA_Code: E192; U/M: EA; AEC Category: Q200
signal-integrity model Resistor
simulation model Resistor
footprint 0603
footprint 0603M
footprint 0603L
footprint 0603_HV
footprint 0603S
pins: 1, 2

## RT0603DRE072K94L
designator R?  ValueDisplayed: 2.94k  (hidden comment: RT0603DRE072K94L)
RES, 2.94 k, 0.5%, 0.1 W, 0603; Manufacturer: Yageo America; CompType: Resistor; Value: 2.94k; Res_ohm: 2940; Value_Code: 2k94; Tolerance_%: 0.5; Power_W: 0.1; Value2: 0.1W; VDC_V: 75; TempCo: 50 ppm/C; SizeArea_mm2: 1.28; SizeX_mm: 1.6; SizeY_mm: 0.8; SizeZ_mm: 1; EIA_Code: E192; U/M: EA; AEC Category: Q200
signal-integrity model Resistor
simulation model Resistor
footprint 0603
footprint 0603M
footprint 0603L
footprint 0603_HV
footprint 0603S
pins: 1, 2

## RT0603DRE072K98L
designator R?  ValueDisplayed: 2.98k  (hidden comment: RT0603DRE072K98L)
RES, 2.98 k, 0.5%, 0.1 W, 0603; Manufacturer: Yageo America; CompType: Resistor; Value: 2.98k; Res_ohm: 2980; Value_Code: 2k98; Tolerance_%: 0.5; Power_W: 0.1; Value2: 0.1W; VDC_V: 75; TempCo: 50 ppm/C; SizeArea_mm2: 1.28; SizeX_mm: 1.6; SizeY_mm: 0.8; SizeZ_mm: 1; EIA_Code: E192; U/M: EA; AEC Category: Q200
signal-integrity model Resistor
simulation model Resistor
footprint 0603
footprint 0603M
footprint 0603L
footprint 0603_HV
footprint 0603S
pins: 1, 2

## RT0603DRE072KL
designator R?  ValueDisplayed: 2.00k  (hidden comment: RT0603DRE072KL)
RES, 2.00 k, 0.5%, 0.1 W, 0603; Manufacturer: Yageo America; CompType: Resistor; Value: 2.00k; Res_ohm: 2000; Value_Code: 2k00; Tolerance_%: 0.5; Power_W: 0.1; Value2: 0.1W; VDC_V: 75; TempCo: 50 ppm/C; SizeArea_mm2: 1.28; SizeX_mm: 1.6; SizeY_mm: 0.8; SizeZ_mm: 1; EIA_Code: E192; U/M: EA; AEC Category: Q200
signal-integrity model Resistor
simulation model Resistor
footprint 0603
footprint 0603M
footprint 0603L
footprint 0603_HV
footprint 0603S
pins: 1, 2

## RT0603DRE072R1L
designator R?  ValueDisplayed: 2.10  (hidden comment: RT0603DRE072R1L)
RES, 2.10, 0.5%, 0.1 W, 0603; Manufacturer: Yageo America; CompType: Resistor; Value: 2.10; Res_ohm: 2.1; Value_Code: 2R10; Tolerance_%: 0.5; Power_W: 0.1; Value2: 0.1W; VDC_V: 75; TempCo: 50 ppm/C; SizeArea_mm2: 1.28; SizeX_mm: 1.6; SizeY_mm: 0.8; SizeZ_mm: 1; EIA_Code: E192; U/M: EA; AEC Category: Q200
signal-integrity model Resistor
simulation model Resistor
footprint 0603
footprint 0603M
footprint 0603L
footprint 0603_HV
footprint 0603S
pins: 1, 2

## RT0603DRE072R03L
designator R?  ValueDisplayed: 2.03  (hidden comment: RT0603DRE072R03L)
RES, 2.03, 0.5%, 0.1 W, 0603; Manufacturer: Yageo America; CompType: Resistor; Value: 2.03; Value_Code: 2R03; Tolerance_%: 0.5; Power_W: 0.1; Value2: 0.1W; VDC_V: 75; TempCo: 50 ppm/C; SizeArea_mm2: 1.28; SizeX_mm: 1.6; SizeY_mm: 0.8; SizeZ_mm: 1; EIA_Code: E192; U/M: EA; AEC Category: Q200
signal-integrity model Resistor
simulation model Resistor
footprint 0603
footprint 0603M
footprint 0603L
footprint 0603_HV
footprint 0603S
pins: 1, 2

## RT0603DRE072R4L
designator R?  ValueDisplayed: 2.40  (hidden comment: RT0603DRE072R4L)
RES, 2.40, 0.5%, 0.1 W, 0603; Manufacturer: Yageo America; CompType: Resistor; Value: 2.40; Res_ohm: 2.4; Value_Code: 2R40; Tolerance_%: 0.5; Power_W: 0.1; Value2: 0.1W; VDC_V: 75; TempCo: 50 ppm/C; SizeArea_mm2: 1.28; SizeX_mm: 1.6; SizeY_mm: 0.8; SizeZ_mm: 1; EIA_Code: E192; U/M: EA; AEC Category: Q200
signal-integrity model Resistor
simulation model Resistor
footprint 0603
footprint 0603M
footprint 0603L
footprint 0603_HV
footprint 0603S
pins: 1, 2

## RT0603DRE072R05L
designator R?  ValueDisplayed: 2.05  (hidden comment: RT0603DRE072R05L)
RES, 2.05, 0.5%, 0.1 W, 0603; Manufacturer: Yageo America; CompType: Resistor; Value: 2.05; Value_Code: 2R05; Tolerance_%: 0.5; Power_W: 0.1; Value2: 0.1W; VDC_V: 75; TempCo: 50 ppm/C; SizeArea_mm2: 1.28; SizeX_mm: 1.6; SizeY_mm: 0.8; SizeZ_mm: 1; EIA_Code: E192; U/M: EA; AEC Category: Q200
signal-integrity model Resistor
simulation model Resistor
footprint 0603
footprint 0603M
footprint 0603L
footprint 0603_HV
footprint 0603S
pins: 1, 2

## RT0603DRE072R08L
designator R?  ValueDisplayed: 2.08  (hidden comment: RT0603DRE072R08L)
RES, 2.08, 0.5%, 0.1 W, 0603; Manufacturer: Yageo America; CompType: Resistor; Value: 2.08; Value_Code: 2R08; Tolerance_%: 0.5; Power_W: 0.1; Value2: 0.1W; VDC_V: 75; TempCo: 50 ppm/C; SizeArea_mm2: 1.28; SizeX_mm: 1.6; SizeY_mm: 0.8; SizeZ_mm: 1; EIA_Code: E192; U/M: EA; AEC Category: Q200
signal-integrity model Resistor
simulation model Resistor
footprint 0603
footprint 0603M
footprint 0603L
footprint 0603_HV
footprint 0603S
pins: 1, 2

## RT0603DRE072R8L
designator R?  ValueDisplayed: 2.80  (hidden comment: RT0603DRE072R8L)
RES, 2.80, 0.5%, 0.1 W, 0603; Manufacturer: Yageo America; CompType: Resistor; Value: 2.80; Res_ohm: 2.8; Value_Code: 2R80; Tolerance_%: 0.5; Power_W: 0.1; Value2: 0.1W; VDC_V: 75; TempCo: 50 ppm/C; SizeArea_mm2: 1.28; SizeX_mm: 1.6; SizeY_mm: 0.8; SizeZ_mm: 1; EIA_Code: E192; U/M: EA; AEC Category: Q200
signal-integrity model Resistor
simulation model Resistor
footprint 0603
footprint 0603M
footprint 0603L
footprint 0603_HV
footprint 0603S
pins: 1, 2

## RT0603DRE072R13L
designator R?  ValueDisplayed: 2.13  (hidden comment: RT0603DRE072R13L)
RES, 2.13, 0.5%, 0.1 W, 0603; Manufacturer: Yageo America; CompType: Resistor; Value: 2.13; Value_Code: 2R13; Tolerance_%: 0.5; Power_W: 0.1; Value2: 0.1W; VDC_V: 75; TempCo: 50 ppm/C; SizeArea_mm2: 1.28; SizeX_mm: 1.6; SizeY_mm: 0.8; SizeZ_mm: 1; EIA_Code: E192; U/M: EA; AEC Category: Q200
signal-integrity model Resistor
simulation model Resistor
footprint 0603
footprint 0603M
footprint 0603L
footprint 0603_HV
footprint 0603S
pins: 1, 2

## RT0603DRE072R15L
designator R?  ValueDisplayed: 2.15  (hidden comment: RT0603DRE072R15L)
RES, 2.15, 0.5%, 0.1 W, 0603; Manufacturer: Yageo America; CompType: Resistor; Value: 2.15; Value_Code: 2R15; Tolerance_%: 0.5; Power_W: 0.1; Value2: 0.1W; VDC_V: 75; TempCo: 50 ppm/C; SizeArea_mm2: 1.28; SizeX_mm: 1.6; SizeY_mm: 0.8; SizeZ_mm: 1; EIA_Code: E192; U/M: EA; AEC Category: Q200
signal-integrity model Resistor
simulation model Resistor
footprint 0603
footprint 0603M
footprint 0603L
footprint 0603_HV
footprint 0603S
pins: 1, 2

## RT0603DRE072R18L
designator R?  ValueDisplayed: 2.18  (hidden comment: RT0603DRE072R18L)
RES, 2.18, 0.5%, 0.1 W, 0603; Manufacturer: Yageo America; CompType: Resistor; Value: 2.18; Value_Code: 2R18; Tolerance_%: 0.5; Power_W: 0.1; Value2: 0.1W; VDC_V: 75; TempCo: 50 ppm/C; SizeArea_mm2: 1.28; SizeX_mm: 1.6; SizeY_mm: 0.8; SizeZ_mm: 1; EIA_Code: E192; U/M: EA; AEC Category: Q200
signal-integrity model Resistor
simulation model Resistor
footprint 0603
footprint 0603M
footprint 0603L
footprint 0603_HV
footprint 0603S
pins: 1, 2

## RT0603DRE072R21L
designator R?  ValueDisplayed: 2.21  (hidden comment: RT0603DRE072R21L)
RES, 2.21, 0.5%, 0.1 W, 0603; Manufacturer: Yageo America; CompType: Resistor; Value: 2.21; Value_Code: 2R21; Tolerance_%: 0.5; Power_W: 0.1; Value2: 0.1W; VDC_V: 75; TempCo: 50 ppm/C; SizeArea_mm2: 1.28; SizeX_mm: 1.6; SizeY_mm: 0.8; SizeZ_mm: 1; EIA_Code: E192; U/M: EA; AEC Category: Q200
signal-integrity model Resistor
simulation model Resistor
footprint 0603
footprint 0603M
footprint 0603L
footprint 0603_HV
footprint 0603S
pins: 1, 2

## RT0603DRE072R23L
designator R?  ValueDisplayed: 2.23  (hidden comment: RT0603DRE072R23L)
RES, 2.23, 0.5%, 0.1 W, 0603; Manufacturer: Yageo America; CompType: Resistor; Value: 2.23; Value_Code: 2R23; Tolerance_%: 0.5; Power_W: 0.1; Value2: 0.1W; VDC_V: 75; TempCo: 50 ppm/C; SizeArea_mm2: 1.28; SizeX_mm: 1.6; SizeY_mm: 0.8; SizeZ_mm: 1; EIA_Code: E192; U/M: EA; AEC Category: Q200
signal-integrity model Resistor
simulation model Resistor
footprint 0603
footprint 0603M
footprint 0603L
footprint 0603_HV
footprint 0603S
pins: 1, 2

## RT0603DRE072R26L
designator R?  ValueDisplayed: 2.26  (hidden comment: RT0603DRE072R26L)
RES, 2.26, 0.5%, 0.1 W, 0603; Manufacturer: Yageo America; CompType: Resistor; Value: 2.26; Value_Code: 2R26; Tolerance_%: 0.5; Power_W: 0.1; Value2: 0.1W; VDC_V: 75; TempCo: 50 ppm/C; SizeArea_mm2: 1.28; SizeX_mm: 1.6; SizeY_mm: 0.8; SizeZ_mm: 1; EIA_Code: E192; U/M: EA; AEC Category: Q200
signal-integrity model Resistor
simulation model Resistor
footprint 0603
footprint 0603M
footprint 0603L
footprint 0603_HV
footprint 0603S
pins: 1, 2

## RT0603DRE072R29L
designator R?  ValueDisplayed: 2.29  (hidden comment: RT0603DRE072R29L)
RES, 2.29, 0.5%, 0.1 W, 0603; Manufacturer: Yageo America; CompType: Resistor; Value: 2.29; Value_Code: 2R29; Tolerance_%: 0.5; Power_W: 0.1; Value2: 0.1W; VDC_V: 75; TempCo: 50 ppm/C; SizeArea_mm2: 1.28; SizeX_mm: 1.6; SizeY_mm: 0.8; SizeZ_mm: 1; EIA_Code: E192; U/M: EA; AEC Category: Q200
signal-integrity model Resistor
simulation model Resistor
footprint 0603
footprint 0603M
footprint 0603L
footprint 0603_HV
footprint 0603S
pins: 1, 2

## RT0603DRE072R32L
designator R?  ValueDisplayed: 2.32  (hidden comment: RT0603DRE072R32L)
RES, 2.32, 0.5%, 0.1 W, 0603; Manufacturer: Yageo America; CompType: Resistor; Value: 2.32; Value_Code: 2R32; Tolerance_%: 0.5; Power_W: 0.1; Value2: 0.1W; VDC_V: 75; TempCo: 50 ppm/C; SizeArea_mm2: 1.28; SizeX_mm: 1.6; SizeY_mm: 0.8; SizeZ_mm: 1; EIA_Code: E192; U/M: EA; AEC Category: Q200
signal-integrity model Resistor
simulation model Resistor
footprint 0603
footprint 0603M
footprint 0603L
footprint 0603_HV
footprint 0603S
pins: 1, 2

## RT0603DRE072R34L
designator R?  ValueDisplayed: 2.34  (hidden comment: RT0603DRE072R34L)
RES, 2.34, 0.5%, 0.1 W, 0603; Manufacturer: Yageo America; CompType: Resistor; Value: 2.34; Value_Code: 2R34; Tolerance_%: 0.5; Power_W: 0.1; Value2: 0.1W; VDC_V: 75; TempCo: 50 ppm/C; SizeArea_mm2: 1.28; SizeX_mm: 1.6; SizeY_mm: 0.8; SizeZ_mm: 1; EIA_Code: E192; U/M: EA; AEC Category: Q200
signal-integrity model Resistor
simulation model Resistor
footprint 0603
footprint 0603M
footprint 0603L
footprint 0603_HV
footprint 0603S
pins: 1, 2

## RT0603DRE072R37L
designator R?  ValueDisplayed: 2.37  (hidden comment: RT0603DRE072R37L)
RES, 2.37, 0.5%, 0.1 W, 0603; Manufacturer: Yageo America; CompType: Resistor; Value: 2.37; Value_Code: 2R37; Tolerance_%: 0.5; Power_W: 0.1; Value2: 0.1W; VDC_V: 75; TempCo: 50 ppm/C; SizeArea_mm2: 1.28; SizeX_mm: 1.6; SizeY_mm: 0.8; SizeZ_mm: 1; EIA_Code: E192; U/M: EA; AEC Category: Q200
signal-integrity model Resistor
simulation model Resistor
footprint 0603
footprint 0603M
footprint 0603L
footprint 0603_HV
footprint 0603S
pins: 1, 2

## RT0603DRE072R43L
designator R?  ValueDisplayed: 2.43  (hidden comment: RT0603DRE072R43L)
RES, 2.43, 0.5%, 0.1 W, 0603; Manufacturer: Yageo America; CompType: Resistor; Value: 2.43; Value_Code: 2R43; Tolerance_%: 0.5; Power_W: 0.1; Value2: 0.1W; VDC_V: 75; TempCo: 50 ppm/C; SizeArea_mm2: 1.28; SizeX_mm: 1.6; SizeY_mm: 0.8; SizeZ_mm: 1; EIA_Code: E192; U/M: EA; AEC Category: Q200
signal-integrity model Resistor
simulation model Resistor
footprint 0603
footprint 0603M
footprint 0603L
footprint 0603_HV
footprint 0603S
pins: 1, 2

## RT0603DRE072R46L
designator R?  ValueDisplayed: 2.46  (hidden comment: RT0603DRE072R46L)
RES, 2.46, 0.5%, 0.1 W, 0603; Manufacturer: Yageo America; CompType: Resistor; Value: 2.46; Value_Code: 2R46; Tolerance_%: 0.5; Power_W: 0.1; Value2: 0.1W; VDC_V: 75; TempCo: 50 ppm/C; SizeArea_mm2: 1.28; SizeX_mm: 1.6; SizeY_mm: 0.8; SizeZ_mm: 1; EIA_Code: E192; U/M: EA; AEC Category: Q200
signal-integrity model Resistor
simulation model Resistor
footprint 0603
footprint 0603M
footprint 0603L
footprint 0603_HV
footprint 0603S
pins: 1, 2

## RT0603DRE072R49L
designator R?  ValueDisplayed: 2.49  (hidden comment: RT0603DRE072R49L)
RES, 2.49, 0.5%, 0.1 W, 0603; Manufacturer: Yageo America; CompType: Resistor; Value: 2.49; Value_Code: 2R49; Tolerance_%: 0.5; Power_W: 0.1; Value2: 0.1W; VDC_V: 75; TempCo: 50 ppm/C; SizeArea_mm2: 1.28; SizeX_mm: 1.6; SizeY_mm: 0.8; SizeZ_mm: 1; EIA_Code: E192; U/M: EA; AEC Category: Q200
signal-integrity model Resistor
simulation model Resistor
footprint 0603
footprint 0603M
footprint 0603L
footprint 0603_HV
footprint 0603S
pins: 1, 2

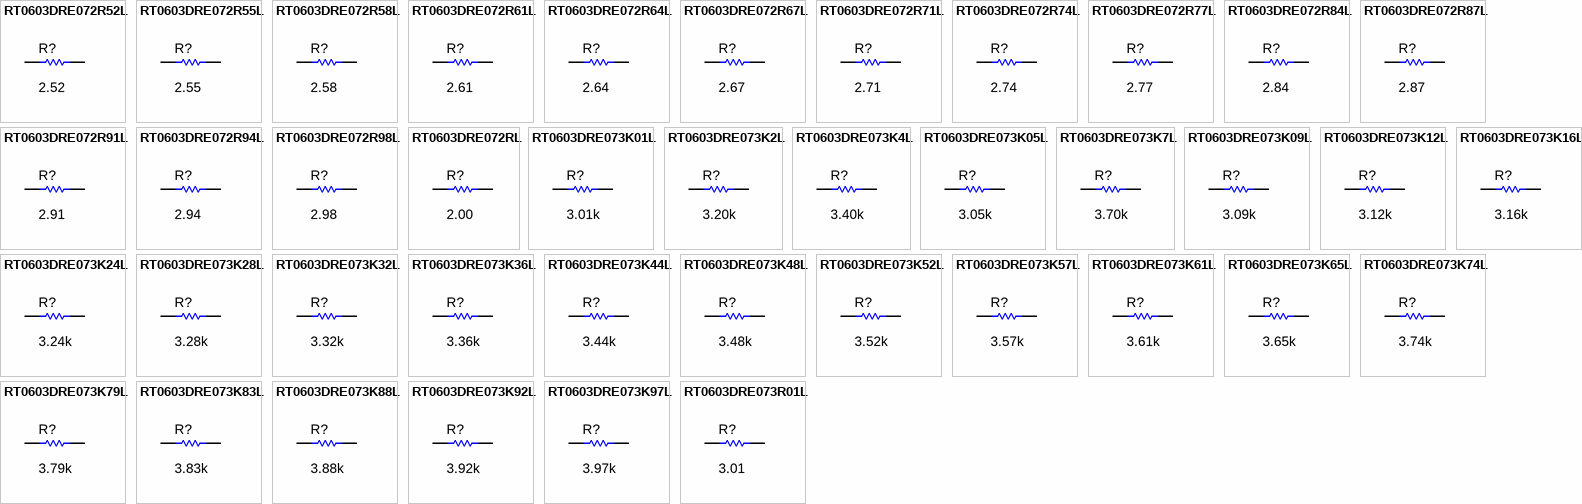
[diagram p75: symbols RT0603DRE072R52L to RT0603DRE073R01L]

## RT0603DRE072R52L
designator R?  ValueDisplayed: 2.52  (hidden comment: RT0603DRE072R52L)
RES, 2.52, 0.5%, 0.1 W, 0603; Manufacturer: Yageo America; CompType: Resistor; Value: 2.52; Value_Code: 2R52; Tolerance_%: 0.5; Power_W: 0.1; Value2: 0.1W; VDC_V: 75; TempCo: 50 ppm/C; SizeArea_mm2: 1.28; SizeX_mm: 1.6; SizeY_mm: 0.8; SizeZ_mm: 1; EIA_Code: E192; U/M: EA; AEC Category: Q200
signal-integrity model Resistor
simulation model Resistor
footprint 0603
footprint 0603M
footprint 0603L
footprint 0603_HV
footprint 0603S
pins: 1, 2

## RT0603DRE072R55L
designator R?  ValueDisplayed: 2.55  (hidden comment: RT0603DRE072R55L)
RES, 2.55, 0.5%, 0.1 W, 0603; Manufacturer: Yageo America; CompType: Resistor; Value: 2.55; Value_Code: 2R55; Tolerance_%: 0.5; Power_W: 0.1; Value2: 0.1W; VDC_V: 75; TempCo: 50 ppm/C; SizeArea_mm2: 1.28; SizeX_mm: 1.6; SizeY_mm: 0.8; SizeZ_mm: 1; EIA_Code: E192; U/M: EA; AEC Category: Q200
signal-integrity model Resistor
simulation model Resistor
footprint 0603
footprint 0603M
footprint 0603L
footprint 0603_HV
footprint 0603S
pins: 1, 2

## RT0603DRE072R58L
designator R?  ValueDisplayed: 2.58  (hidden comment: RT0603DRE072R58L)
RES, 2.58, 0.5%, 0.1 W, 0603; Manufacturer: Yageo America; CompType: Resistor; Value: 2.58; Value_Code: 2R58; Tolerance_%: 0.5; Power_W: 0.1; Value2: 0.1W; VDC_V: 75; TempCo: 50 ppm/C; SizeArea_mm2: 1.28; SizeX_mm: 1.6; SizeY_mm: 0.8; SizeZ_mm: 1; EIA_Code: E192; U/M: EA; AEC Category: Q200
signal-integrity model Resistor
simulation model Resistor
footprint 0603
footprint 0603M
footprint 0603L
footprint 0603_HV
footprint 0603S
pins: 1, 2

## RT0603DRE072R61L
designator R?  ValueDisplayed: 2.61  (hidden comment: RT0603DRE072R61L)
RES, 2.61, 0.5%, 0.1 W, 0603; Manufacturer: Yageo America; CompType: Resistor; Value: 2.61; Value_Code: 2R61; Tolerance_%: 0.5; Power_W: 0.1; Value2: 0.1W; VDC_V: 75; TempCo: 50 ppm/C; SizeArea_mm2: 1.28; SizeX_mm: 1.6; SizeY_mm: 0.8; SizeZ_mm: 1; EIA_Code: E192; U/M: EA; AEC Category: Q200
signal-integrity model Resistor
simulation model Resistor
footprint 0603
footprint 0603M
footprint 0603L
footprint 0603_HV
footprint 0603S
pins: 1, 2

## RT0603DRE072R64L
designator R?  ValueDisplayed: 2.64  (hidden comment: RT0603DRE072R64L)
RES, 2.64, 0.5%, 0.1 W, 0603; Manufacturer: Yageo America; CompType: Resistor; Value: 2.64; Value_Code: 2R64; Tolerance_%: 0.5; Power_W: 0.1; Value2: 0.1W; VDC_V: 75; TempCo: 50 ppm/C; SizeArea_mm2: 1.28; SizeX_mm: 1.6; SizeY_mm: 0.8; SizeZ_mm: 1; EIA_Code: E192; U/M: EA; AEC Category: Q200
signal-integrity model Resistor
simulation model Resistor
footprint 0603
footprint 0603M
footprint 0603L
footprint 0603_HV
footprint 0603S
pins: 1, 2

## RT0603DRE072R67L
designator R?  ValueDisplayed: 2.67  (hidden comment: RT0603DRE072R67L)
RES, 2.67, 0.5%, 0.1 W, 0603; Manufacturer: Yageo America; CompType: Resistor; Value: 2.67; Value_Code: 2R67; Tolerance_%: 0.5; Power_W: 0.1; Value2: 0.1W; VDC_V: 75; TempCo: 50 ppm/C; SizeArea_mm2: 1.28; SizeX_mm: 1.6; SizeY_mm: 0.8; SizeZ_mm: 1; EIA_Code: E192; U/M: EA; AEC Category: Q200
signal-integrity model Resistor
simulation model Resistor
footprint 0603
footprint 0603M
footprint 0603L
footprint 0603_HV
footprint 0603S
pins: 1, 2

## RT0603DRE072R71L
designator R?  ValueDisplayed: 2.71  (hidden comment: RT0603DRE072R71L)
RES, 2.71, 0.5%, 0.1 W, 0603; Manufacturer: Yageo America; CompType: Resistor; Value: 2.71; Value_Code: 2R71; Tolerance_%: 0.5; Power_W: 0.1; Value2: 0.1W; VDC_V: 75; TempCo: 50 ppm/C; SizeArea_mm2: 1.28; SizeX_mm: 1.6; SizeY_mm: 0.8; SizeZ_mm: 1; EIA_Code: E192; U/M: EA; AEC Category: Q200
signal-integrity model Resistor
simulation model Resistor
footprint 0603
footprint 0603M
footprint 0603L
footprint 0603_HV
footprint 0603S
pins: 1, 2

## RT0603DRE072R74L
designator R?  ValueDisplayed: 2.74  (hidden comment: RT0603DRE072R74L)
RES, 2.74, 0.5%, 0.1 W, 0603; Manufacturer: Yageo America; CompType: Resistor; Value: 2.74; Value_Code: 2R74; Tolerance_%: 0.5; Power_W: 0.1; Value2: 0.1W; VDC_V: 75; TempCo: 50 ppm/C; SizeArea_mm2: 1.28; SizeX_mm: 1.6; SizeY_mm: 0.8; SizeZ_mm: 1; EIA_Code: E192; U/M: EA; AEC Category: Q200
signal-integrity model Resistor
simulation model Resistor
footprint 0603
footprint 0603M
footprint 0603L
footprint 0603_HV
footprint 0603S
pins: 1, 2

## RT0603DRE072R77L
designator R?  ValueDisplayed: 2.77  (hidden comment: RT0603DRE072R77L)
RES, 2.77, 0.5%, 0.1 W, 0603; Manufacturer: Yageo America; CompType: Resistor; Value: 2.77; Value_Code: 2R77; Tolerance_%: 0.5; Power_W: 0.1; Value2: 0.1W; VDC_V: 75; TempCo: 50 ppm/C; SizeArea_mm2: 1.28; SizeX_mm: 1.6; SizeY_mm: 0.8; SizeZ_mm: 1; EIA_Code: E192; U/M: EA; AEC Category: Q200
signal-integrity model Resistor
simulation model Resistor
footprint 0603
footprint 0603M
footprint 0603L
footprint 0603_HV
footprint 0603S
pins: 1, 2

## RT0603DRE072R84L
designator R?  ValueDisplayed: 2.84  (hidden comment: RT0603DRE072R84L)
RES, 2.84, 0.5%, 0.1 W, 0603; Manufacturer: Yageo America; CompType: Resistor; Value: 2.84; Value_Code: 2R84; Tolerance_%: 0.5; Power_W: 0.1; Value2: 0.1W; VDC_V: 75; TempCo: 50 ppm/C; SizeArea_mm2: 1.28; SizeX_mm: 1.6; SizeY_mm: 0.8; SizeZ_mm: 1; EIA_Code: E192; U/M: EA; AEC Category: Q200
signal-integrity model Resistor
simulation model Resistor
footprint 0603
footprint 0603M
footprint 0603L
footprint 0603_HV
footprint 0603S
pins: 1, 2

## RT0603DRE072R87L
designator R?  ValueDisplayed: 2.87  (hidden comment: RT0603DRE072R87L)
RES, 2.87, 0.5%, 0.1 W, 0603; Manufacturer: Yageo America; CompType: Resistor; Value: 2.87; Value_Code: 2R87; Tolerance_%: 0.5; Power_W: 0.1; Value2: 0.1W; VDC_V: 75; TempCo: 50 ppm/C; SizeArea_mm2: 1.28; SizeX_mm: 1.6; SizeY_mm: 0.8; SizeZ_mm: 1; EIA_Code: E192; U/M: EA; AEC Category: Q200
signal-integrity model Resistor
simulation model Resistor
footprint 0603
footprint 0603M
footprint 0603L
footprint 0603_HV
footprint 0603S
pins: 1, 2

## RT0603DRE072R91L
designator R?  ValueDisplayed: 2.91  (hidden comment: RT0603DRE072R91L)
RES, 2.91, 0.5%, 0.1 W, 0603; Manufacturer: Yageo America; CompType: Resistor; Value: 2.91; Value_Code: 2R91; Tolerance_%: 0.5; Power_W: 0.1; Value2: 0.1W; VDC_V: 75; TempCo: 50 ppm/C; SizeArea_mm2: 1.28; SizeX_mm: 1.6; SizeY_mm: 0.8; SizeZ_mm: 1; EIA_Code: E192; U/M: EA; AEC Category: Q200
signal-integrity model Resistor
simulation model Resistor
footprint 0603
footprint 0603M
footprint 0603L
footprint 0603_HV
footprint 0603S
pins: 1, 2

## RT0603DRE072R94L
designator R?  ValueDisplayed: 2.94  (hidden comment: RT0603DRE072R94L)
RES, 2.94, 0.5%, 0.1 W, 0603; Manufacturer: Yageo America; CompType: Resistor; Value: 2.94; Value_Code: 2R94; Tolerance_%: 0.5; Power_W: 0.1; Value2: 0.1W; VDC_V: 75; TempCo: 50 ppm/C; SizeArea_mm2: 1.28; SizeX_mm: 1.6; SizeY_mm: 0.8; SizeZ_mm: 1; EIA_Code: E192; U/M: EA; AEC Category: Q200
signal-integrity model Resistor
simulation model Resistor
footprint 0603
footprint 0603M
footprint 0603L
footprint 0603_HV
footprint 0603S
pins: 1, 2

## RT0603DRE072R98L
designator R?  ValueDisplayed: 2.98  (hidden comment: RT0603DRE072R98L)
RES, 2.98, 0.5%, 0.1 W, 0603; Manufacturer: Yageo America; CompType: Resistor; Value: 2.98; Value_Code: 2R98; Tolerance_%: 0.5; Power_W: 0.1; Value2: 0.1W; VDC_V: 75; TempCo: 50 ppm/C; SizeArea_mm2: 1.28; SizeX_mm: 1.6; SizeY_mm: 0.8; SizeZ_mm: 1; EIA_Code: E192; U/M: EA; AEC Category: Q200
signal-integrity model Resistor
simulation model Resistor
footprint 0603
footprint 0603M
footprint 0603L
footprint 0603_HV
footprint 0603S
pins: 1, 2

## RT0603DRE072RL
designator R?  ValueDisplayed: 2.00  (hidden comment: RT0603DRE072RL)
RES, 2.00, 0.5%, 0.1 W, 0603; Manufacturer: Yageo America; CompType: Resistor; Value: 2.00; Res_ohm: 2; Value_Code: 2R00; Tolerance_%: 0.5; Power_W: 0.1; Value2: 0.1W; VDC_V: 75; TempCo: 50 ppm/C; SizeArea_mm2: 1.28; SizeX_mm: 1.6; SizeY_mm: 0.8; SizeZ_mm: 1; EIA_Code: E192; U/M: EA; AEC Category: Q200
signal-integrity model Resistor
simulation model Resistor
footprint 0603
footprint 0603M
footprint 0603L
footprint 0603_HV
footprint 0603S
pins: 1, 2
